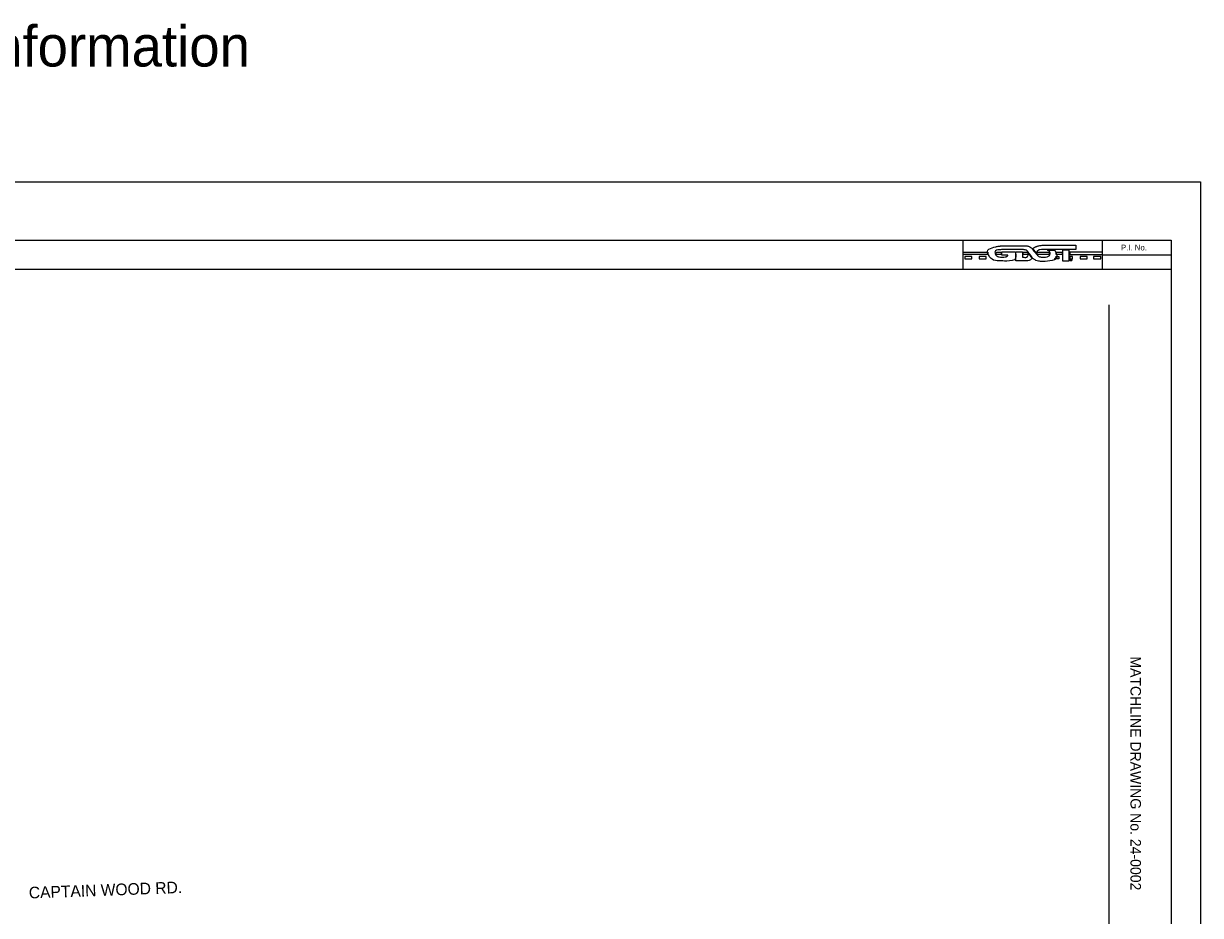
# Model space of a CAD drawing. Extents: x 2157704 to 2158404, y 1040586 to 1041166.
# Drawn here: x 2158000.4 to 2158404, y 1040860.6 to 1041166.5 of the extents above; entities that cross this region are included whole.
import ezdxf

# ---------------------------------------------------------------- set-up
doc = ezdxf.new("R2010")
doc.units = 0
for name, color, linetype in [('SHT_B_20-Staging-Details', 7, 'Continuous'), ('SHT_B_Grid-Major-Line', 7, 'Continuous'), ('SHT_B_MainLine-Text', 7, 'Continuous'), ('SHT_B_Major-Elevation-Tic-Line', 7, 'Continuous'), ('SHT_B_North-Arrow', 7, 'Continuous'), ('SHT_B_Plot-Sub-Text', 7, 'Continuous'), ('UTLE_E_UG-Wat-Line-30-Qual-B-50', 7, 'Continuous'), ('UTLE_E_UG-Wat-Line-30-Qual-C-50', 7, 'Continuous')]:
    doc.layers.add(name, color=color, linetype=linetype)

msp = doc.modelspace()

# ---------------------------------------------------------------- linework, layer by layer
at = {"layer": 'SHT_B_Grid-Major-Line'}
for points in [[(2158359, 1041085.06), (2158359, 1041088.75), (2158356.73, 1041088.75), (2158356.73, 1041085.06), (2158359, 1041085.06), (2158359, 1041085.06)], [(2158359.19, 1041088.04), (2158359.19, 1041087.29), (2158370.35, 1041087.29), (2158370.35, 1041088.04), (2158359.19, 1041088.04), (2158359.19, 1041088.04)], [(2158323.16, 1041085.72), (2158325.6, 1041085.72), (2158325.6, 1041086.55), (2158323.16, 1041086.55), (2158323.16, 1041085.72), (2158323.16, 1041085.72)], [(2158330.53, 1041086.55), (2158328.09, 1041086.55), (2158328.09, 1041085.72), (2158330.53, 1041085.72), (2158330.53, 1041086.55), (2158330.53, 1041086.55)], [(2158360.06, 1041086.55), (2158359.21, 1041086.55), (2158359.21, 1041085.72), (2158360.06, 1041085.72), (2158360.06, 1041086.55), (2158360.06, 1041086.55)], [(2158365.18, 1041086.55), (2158362.74, 1041086.55), (2158362.74, 1041085.72), (2158365.18, 1041085.72), (2158365.18, 1041086.55), (2158365.18, 1041086.55)], [(2158367.34, 1041085.72), (2158369.78, 1041085.72), (2158369.78, 1041086.55), (2158367.34, 1041086.55), (2158367.34, 1041085.72), (2158367.34, 1041085.72)]]:
    msp.add_lwpolyline(points, dxfattribs=at)
for points in [[(2158322.64, 1041087.29), (2158322.64, 1041087.29), (2158331.07, 1041087.29), (2158331.07, 1041087.29), (2158331.05, 1041087.42), (2158331.03, 1041087.57), (2158331.03, 1041087.73), (2158331.04, 1041087.84), (2158331.07, 1041087.94), (2158331.1, 1041088.04), (2158331.1, 1041088.04), (2158322.64, 1041088.04), (2158322.64, 1041088.04), (2158322.64, 1041088.04), (2158322.64, 1041087.29), (2158322.64, 1041087.29), (2158322.64, 1041087.29), (2158322.64, 1041087.29), (2158322.64, 1041087.29)], [(2158353.99, 1041088.75), (2158353.99, 1041088.75), (2158351.44, 1041088.75), (2158351.44, 1041088.75), (2158352.02, 1041088.5), (2158352.4, 1041088.1), (2158352.4, 1041087.65), (2158352.4, 1041086.94), (2158351.46, 1041086.35), (2158350.27, 1041086.31), (2158350.27, 1041086.31), (2158349.43, 1041086.36), (2158349.43, 1041086.36), (2158348.8, 1041086.48), (2158348.29, 1041086.75), (2158348.03, 1041087.1), (2158347.55, 1041087.55), (2158346.86, 1041088.46), (2158346.39, 1041089.11), (2158346.26, 1041089.29), (2158346.11, 1041089.44), (2158345.95, 1041089.57), (2158345.57, 1041089.85), (2158345.19, 1041090.02), (2158344.88, 1041090.13), (2158344.6, 1041090.21), (2158344.31, 1041090.25), (2158344.12, 1041090.27), (2158344.12, 1041090.27), (2158336.42, 1041090.27), (2158336.42, 1041090.27), (2158336.11, 1041090.25), (2158335.63, 1041090.21), (2158335.32, 1041090.18), (2158334.65, 1041090.09), (2158333.99, 1041089.95), (2158333.65, 1041089.88), (2158330.29, 1041088.9), (2158331.49, 1041086.8), (2158331.49, 1041086.8), (2158332.75, 1041085.04), (2158335.87, 1041085.06), (2158335.87, 1041085.06), (2158341.18, 1041084.86), (2158340.47, 1041088.22), (2158340.47, 1041088.22), (2158340.47, 1041088.22), (2158335.87, 1041088.22), (2158335.87, 1041088.22), (2158335.87, 1041088.22), (2158335.87, 1041087.08), (2158335.87, 1041087.08), (2158335.87, 1041087.08), (2158337.89, 1041087.08), (2158337.89, 1041087.08), (2158337.9, 1041086.76), (2158337.64, 1041086.57), (2158337.28, 1041086.47), (2158337.28, 1041086.47), (2158337.28, 1041086.47), (2158337.28, 1041086.47), (2158335.86, 1041086.25), (2158334.9, 1041086.44), (2158334.5, 1041086.56), (2158334.45, 1041086.58), (2158334.4, 1041086.59), (2158334.35, 1041086.61), (2158333.84, 1041086.88), (2158333.69, 1041087.28), (2158333.69, 1041087.28), (2158333.21, 1041088.77), (2158335.87, 1041088.93), (2158335.87, 1041088.93), (2158335.87, 1041088.93), (2158343.19, 1041088.93), (2158343.19, 1041088.93), (2158343.95, 1041088.9), (2158344.4, 1041088.7), (2158344.65, 1041088.43), (2158344.65, 1041088.43), (2158344.66, 1041088.44), (2158344.66, 1041088.44), (2158344.66, 1041088.44), (2158346.28, 1041086.2), (2158346.28, 1041086.2), (2158346.42, 1041086.03), (2158346.69, 1041085.75), (2158347.01, 1041085.52), (2158347.52, 1041085.25), (2158348.4, 1041084.93), (2158349.85, 1041084.82), (2158350.11, 1041084.81), (2158350.45, 1041084.81), (2158350.82, 1041084.84), (2158355.51, 1041085.43), (2158354.21, 1041088.32), (2158353.99, 1041088.75), (2158353.99, 1041088.75), (2158353.99, 1041088.75), (2158353.99, 1041088.75)], [(2158334.05, 1041087.29), (2158334.05, 1041087.29), (2158335.68, 1041087.29), (2158335.68, 1041087.29), (2158335.68, 1041087.29), (2158335.68, 1041088.04), (2158335.68, 1041088.04), (2158335.68, 1041088.04), (2158334.06, 1041088.04), (2158334.06, 1041088.04), (2158333.93, 1041087.93), (2158333.68, 1041087.62), (2158334.05, 1041087.29), (2158334.05, 1041087.29), (2158334.05, 1041087.29), (2158334.05, 1041087.29)], [(2158340.66, 1041088.22), (2158340.66, 1041088.22), (2158340.66, 1041085.06), (2158340.66, 1041085.06), (2158340.66, 1041085.06), (2158344.11, 1041085.06), (2158344.11, 1041085.06), (2158345.37, 1041085.06), (2158346.04, 1041085.72), (2158346.22, 1041085.92), (2158346.22, 1041085.92), (2158344.97, 1041087.65), (2158344.97, 1041087.65), (2158344.98, 1041087.32), (2158344.88, 1041087.05), (2158344.88, 1041087.05), (2158344.58, 1041086.14), (2158342.93, 1041086.39), (2158342.93, 1041086.39), (2158342.93, 1041086.39), (2158342.93, 1041088.22), (2158342.93, 1041088.22), (2158342.93, 1041088.22), (2158340.66, 1041088.22), (2158340.66, 1041088.22), (2158340.66, 1041088.22), (2158340.66, 1041088.22), (2158340.66, 1041088.22)], [(2158344.63, 1041088.04), (2158344.63, 1041088.04), (2158343.15, 1041088.04), (2158343.15, 1041088.04), (2158343.15, 1041088.04), (2158343.15, 1041087.29), (2158343.15, 1041087.29), (2158343.15, 1041087.29), (2158344.64, 1041087.29), (2158344.64, 1041087.29), (2158344.98, 1041087.62), (2158344.74, 1041087.93), (2158344.63, 1041088.04), (2158344.63, 1041088.04), (2158344.63, 1041088.04), (2158344.63, 1041088.04)], [(2158347.83, 1041087.62), (2158347.83, 1041087.63), (2158347.83, 1041087.64), (2158347.83, 1041087.65), (2158347.83, 1041088.39), (2158348.85, 1041089), (2158350.11, 1041089), (2158350.29, 1041089), (2158350.47, 1041088.98), (2158350.63, 1041088.96), (2158350.63, 1041088.96), (2158361.27, 1041088.96), (2158361.27, 1041088.96), (2158361.27, 1041088.96), (2158361.27, 1041090.44), (2158361.27, 1041090.44), (2158361.27, 1041090.44), (2158350.56, 1041090.44), (2158350.56, 1041090.44), (2158350.45, 1041090.44), (2158350.35, 1041090.44), (2158350.25, 1041090.44), (2158350.25, 1041090.44), (2158350.18, 1041090.44), (2158350.18, 1041090.44), (2158350.18, 1041090.44), (2158350.18, 1041090.44), (2158350.18, 1041090.44), (2158349.29, 1041090.42), (2158348.59, 1041090.29), (2158348.06, 1041090.12), (2158347.92, 1041090.08), (2158347.79, 1041090.03), (2158347.67, 1041089.99), (2158347.27, 1041089.83), (2158347, 1041089.65), (2158346.84, 1041089.51), (2158346.68, 1041089.39), (2158346.62, 1041089.3), (2158346.62, 1041089.3), (2158346.62, 1041089.3), (2158346.63, 1041089.3), (2158346.63, 1041089.3), (2158346.61, 1041089.28), (2158346.59, 1041089.25), (2158346.57, 1041089.23), (2158346.93, 1041088.74), (2158347.41, 1041088.09), (2158347.83, 1041087.62), (2158347.83, 1041087.62), (2158347.83, 1041087.62), (2158347.83, 1041087.62)], [(2158349.97, 1041088.04), (2158349.97, 1041088.04), (2158348.18, 1041088.04), (2158348.18, 1041088.04), (2158348.05, 1041087.93), (2158347.77, 1041087.62), (2158348.18, 1041087.29), (2158348.18, 1041087.29), (2158349.97, 1041087.29), (2158349.97, 1041087.29), (2158349.97, 1041087.29), (2158349.98, 1041087.29), (2158349.98, 1041087.29), (2158349.98, 1041087.29), (2158351.97, 1041087.29), (2158351.97, 1041087.29), (2158352.43, 1041087.62), (2158352.11, 1041087.93), (2158351.96, 1041088.04), (2158351.96, 1041088.04), (2158349.98, 1041088.04), (2158349.98, 1041088.04), (2158349.98, 1041088.04), (2158349.97, 1041088.04), (2158349.97, 1041088.04), (2158349.97, 1041088.04), (2158349.97, 1041088.04), (2158349.97, 1041088.04)], [(2158356.53, 1041088.04), (2158356.53, 1041088.04), (2158354.49, 1041088.04), (2158354.49, 1041088.04), (2158354.53, 1041087.89), (2158354.55, 1041087.74), (2158354.54, 1041087.59), (2158354.53, 1041087.49), (2158354.51, 1041087.39), (2158354.49, 1041087.29), (2158354.49, 1041087.29), (2158356.53, 1041087.29), (2158356.53, 1041087.29), (2158356.53, 1041087.29), (2158356.53, 1041088.04), (2158356.53, 1041088.04), (2158356.53, 1041088.04), (2158356.53, 1041088.04), (2158356.53, 1041088.04)], [(2158354.24, 1041086.09), (2158354.14, 1041085.94), (2158354.04, 1041085.82), (2158353.95, 1041085.72), (2158353.95, 1041085.72), (2158355.42, 1041085.72), (2158355.42, 1041085.72), (2158355.42, 1041085.72), (2158355.42, 1041086.55), (2158355.42, 1041086.55), (2158355.42, 1041086.55), (2158354.46, 1041086.55), (2158354.46, 1041086.55), (2158354.41, 1041086.4), (2158354.34, 1041086.24), (2158354.24, 1041086.09), (2158354.24, 1041086.09), (2158354.24, 1041086.09), (2158354.24, 1041086.09)], [(2158359.59, 1041085.56), (2158359.46, 1041085.56), (2158359.36, 1041085.46), (2158359.36, 1041085.33), (2158359.36, 1041085.2), (2158359.46, 1041085.09), (2158359.59, 1041085.09), (2158359.72, 1041085.09), (2158359.83, 1041085.2), (2158359.83, 1041085.33), (2158359.83, 1041085.46), (2158359.72, 1041085.56), (2158359.59, 1041085.56), (2158359.59, 1041085.56), (2158359.59, 1041085.56), (2158359.59, 1041085.56), (2158359.59, 1041085.56), (2158359.59, 1041085.56), (2158359.59, 1041085.56)], [(2158359.78, 1041085.33), (2158359.78, 1041085.22), (2158359.69, 1041085.13), (2158359.59, 1041085.13), (2158359.49, 1041085.13), (2158359.41, 1041085.22), (2158359.41, 1041085.33), (2158359.41, 1041085.43), (2158359.49, 1041085.52), (2158359.59, 1041085.52), (2158359.59, 1041085.52), (2158359.59, 1041085.52), (2158359.59, 1041085.52), (2158359.69, 1041085.52), (2158359.78, 1041085.43), (2158359.78, 1041085.33), (2158359.78, 1041085.33), (2158359.78, 1041085.33), (2158359.78, 1041085.33)], [(2158359.46, 1041085.32), (2158359.46, 1041085.25), (2158359.51, 1041085.19), (2158359.6, 1041085.19), (2158359.63, 1041085.19), (2158359.67, 1041085.19), (2158359.7, 1041085.21), (2158359.7, 1041085.21), (2158359.69, 1041085.25), (2158359.69, 1041085.25), (2158359.67, 1041085.24), (2158359.64, 1041085.23), (2158359.61, 1041085.23), (2158359.55, 1041085.23), (2158359.52, 1041085.27), (2158359.52, 1041085.33), (2158359.52, 1041085.39), (2158359.55, 1041085.42), (2158359.61, 1041085.42), (2158359.64, 1041085.42), (2158359.67, 1041085.41), (2158359.68, 1041085.4), (2158359.68, 1041085.4), (2158359.7, 1041085.44), (2158359.7, 1041085.44), (2158359.69, 1041085.46), (2158359.65, 1041085.47), (2158359.61, 1041085.47), (2158359.53, 1041085.47), (2158359.46, 1041085.41), (2158359.46, 1041085.32), (2158359.46, 1041085.32), (2158359.46, 1041085.32), (2158359.46, 1041085.32)]]:
    msp.add_open_spline(points, degree=3, dxfattribs=at)
at = {"layer": 'SHT_B_MainLine-Text'}
msp.add_line((2158372.56, 1041070), (2158372.56, 1040725.2), dxfattribs=at)
at = {"layer": 'SHT_B_North-Arrow'}
for p, q in [((2158322.64, 1041082.17), (2158322.64, 1041092.15)), ((2158370.35, 1041082.17), (2158370.35, 1041092.13)), ((2158370.35, 1041087.15), (2158393.99, 1041087.15)), ((2158393.99, 1041082.15), (2157733.99, 1041082.15)), ((2158383.99, 1041082.15), (2158383.99, 1041082.15)), ((2158383.99, 1041082.15), (2158383.99, 1041082.15)), ((2158383.99, 1041082.15), (2158383.99, 1041082.15)), ((2158383.99, 1041082.15), (2158383.99, 1041082.15)), ((2158383.99, 1040899.89), (2158383.99, 1040899.89)), ((2158383.99, 1040899.89), (2158383.99, 1040899.89))]:
    msp.add_line(p, q, dxfattribs=at)
at = {"layer": 'UTLE_E_UG-Wat-Line-30-Qual-B-50'}
msp.add_lwpolyline([(2157733.99, 1041092.15), (2158393.99, 1041092.15), (2158393.99, 1040672.15), (2157733.99, 1040672.15)], close=True, dxfattribs=at)
at = {"layer": 'UTLE_E_UG-Wat-Line-30-Qual-C-50'}
msp.add_lwpolyline([(2157703.99, 1041112.15), (2158403.99, 1041112.15), (2158403.99, 1040652.15), (2157703.99, 1040652.15)], close=True, dxfattribs=at)

# ---------------------------------------------------------------- texts
at = {"layer": 'SHT_B_20-Staging-Details'}
msp.add_text('CAPTAIN WOOD RD.', height=4, rotation=2.0728, dxfattribs=at).set_placement((2158002.28, 1040866.37))
at = {"layer": 'SHT_B_Major-Elevation-Tic-Line'}
msp.add_text('MATCHLINE DRAWING No. 24-0002', height=3.6, rotation=270, dxfattribs=at).set_placement((2158379.98, 1040949.43))
at = {"layer": 'SHT_B_North-Arrow'}
msp.add_text('Design File and Plot Substitution information', height=14, rotation=0, dxfattribs=at).set_placement((2157709.67, 1041151.73))
at = {"layer": 'SHT_B_Plot-Sub-Text'}
msp.add_text('P.I. No.', height=2, rotation=360, dxfattribs=at).set_placement((2158376.72, 1041088.65))

doc.saveas('drawing.dxf')
